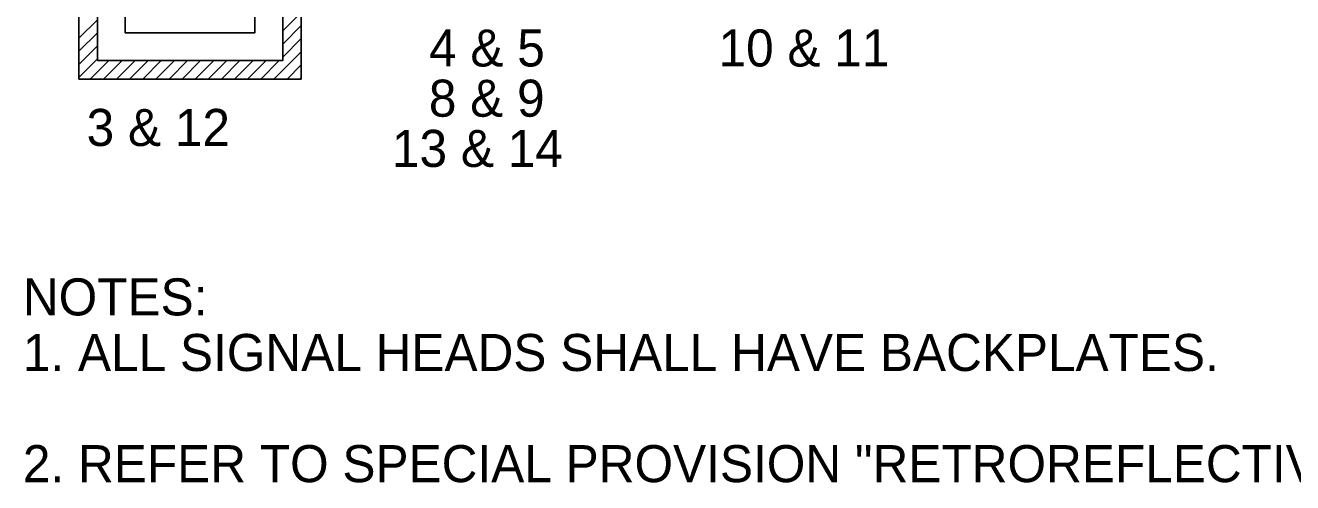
# Model space of a CAD drawing. Extents: x -218554 to 420030, y -565899 to -483460.
# Drawn here: x 419074.8 to 419211.5, y -565425.5 to -565376.2 of the extents above; entities that cross this region are included whole.
import ezdxf

# ---------------------------------------------------------------- set-up
doc = ezdxf.new("R2010")
doc.units = 0
doc.layers.add('T_Drafting', color=7, linetype='Continuous')
doc.layers.add('T_Notes', color=7, linetype='Continuous')

msp = doc.modelspace()

# ---------------------------------------------------------------- linework, layer by layer
at = {"layer": 'T_Drafting'}
for p, q in [((419080.56, -565381.97), (419080.56, -565315.97)), ((419104.56, -565315.97), (419104.56, -565381.97)), ((419085.56, -565362.97), (419085.56, -565376.97)), ((419099.56, -565362.97), (419099.56, -565376.97)), ((419080.56, -565377.56), (419082.56, -565375.56)), ((419102.56, -565376.77), (419104.56, -565374.77)), ((419080.56, -565378.97), (419082.56, -565376.97)), ((419085.56, -565376.97), (419099.56, -565376.97)), ((419102.56, -565378.19), (419104.56, -565376.19)), ((419080.56, -565380.39), (419082.56, -565378.39)), ((419102.56, -565379.6), (419104.56, -565377.6)), ((419080.56, -565381.8), (419082.56, -565379.8)), ((419101.6, -565381.97), (419104.56, -565379.02)), ((419081.8, -565381.97), (419083.8, -565379.97)), ((419083.22, -565381.97), (419085.22, -565379.97)), ((419084.63, -565381.97), (419086.63, -565379.97)), ((419086.04, -565381.97), (419088.04, -565379.97)), ((419087.46, -565381.97), (419089.46, -565379.97)), ((419088.87, -565381.97), (419090.87, -565379.97)), ((419090.29, -565381.97), (419092.29, -565379.97)), ((419091.7, -565381.97), (419093.7, -565379.97)), ((419093.12, -565381.97), (419095.12, -565379.97)), ((419094.53, -565381.97), (419096.53, -565379.97)), ((419095.94, -565381.97), (419097.94, -565379.97)), ((419097.36, -565381.97), (419099.36, -565379.97)), ((419098.77, -565381.97), (419100.77, -565379.97)), ((419100.19, -565381.97), (419102.19, -565379.97)), ((419103.02, -565381.97), (419104.56, -565380.43)), ((419104.56, -565381.97), (419080.56, -565381.97)), ((419104.43, -565381.97), (419104.56, -565381.84))]:
    msp.add_line(p, q, dxfattribs=at)
msp.add_lwpolyline([(419082.56, -565379.97), (419082.56, -565317.97), (419102.56, -565317.97), (419102.56, -565379.97)], close=True, dxfattribs=at)

# ---------------------------------------------------------------- texts
at = {"layer": 'T_Notes'}
for s, p in [('4 & 5', (419118.34, -565380.61)), ('10 & 11', (419149.57, -565380.61)), ('8 & 9', (419118.32, -565386.03)), ('3 & 12', (419081.4, -565389.19)), ('13 & 14', (419114.34, -565391.45)), ('NOTES:', (419074.52, -565407.48)), ('1. ALL SIGNAL HEADS SHALL HAVE BACKPLATES.', (419074.52, -565413.48)), ('2. REFER TO SPECIAL PROVISION "RETROREFLECTIVE BACKPLATES"', (419074.52, -565425.48))]:
    msp.add_text(s, height=4, dxfattribs=at).set_placement(p)

doc.saveas('drawing.dxf')
